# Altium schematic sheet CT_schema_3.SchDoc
size 214 x 189 mm
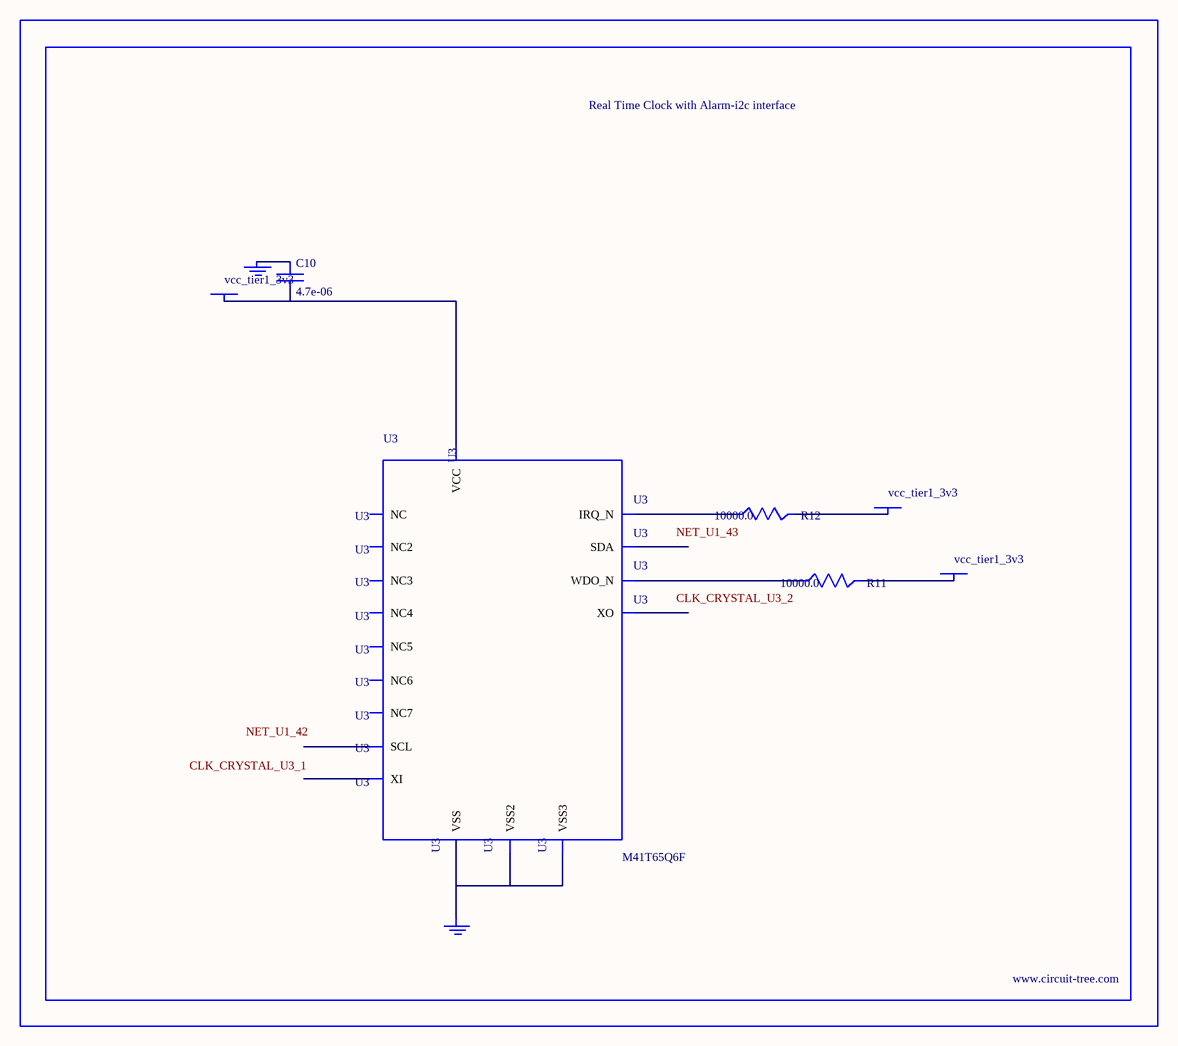
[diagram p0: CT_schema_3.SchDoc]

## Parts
BORDER2  (no value)
C10  4.7e-06  [C0805]
GND_INSTANCE_2_0  (no value)
GND_INSTANCE_2_1  (no value)
POWER_INSTANCE_2_0  vcc_tier1_3v3
POWER_INSTANCE_2_1  vcc_tier1_3v3
POWER_INSTANCE_2_2  vcc_tier1_3v3
R11  10000.0  [R0603]
R12  10000.0  [R0603]
U3  M41T65Q6F  [M41T65_QFN-16]

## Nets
NetC10_1: C10.1 GND_INSTANCE_2_0.0(GND)
NetC10_2: C10.2 POWER_INSTANCE_2_2.0(PWR) U3.14(VCC)
NetGND_INSTANCE_2_1_0: GND_INSTANCE_2_1.0(GND) U3.3(VSS) U3.5(VSS2) U3.17(VSS3)
NetPOWER_INSTANCE_2_0_0: POWER_INSTANCE_2_0.0(PWR) R11.2
NetPOWER_INSTANCE_2_1_0: POWER_INSTANCE_2_1.0(PWR) R12.2
NetR11_1: R11.1 U3.4(WDO_N)
NetR12_1: R12.1 U3.11(IRQ_N)

Not connected (* = marked no-connect by the designer): U3 1(XI) 2(XO) 6(NC) 7(NC2) 8(NC3) 9(SDA) 10(SCL) 12(NC4) 13(NC5) 15(NC6) 16(NC7)

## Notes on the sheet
- Labels drawn without touching a wire or pin: CLK_CRYSTAL_U3_1, CLK_CRYSTAL_U3_2, NET_U1_42, NET_U1_43

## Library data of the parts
BORDER2 = BORDER_PAGE2
C10 = C0805C475K4RACTU
GND_INSTANCE_2_0 GND_INSTANCE_2_1 = GND
POWER_INSTANCE_2_0-POWER_INSTANCE_2_2 = PWR
R11 R12 = RC0603JR-0710KL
